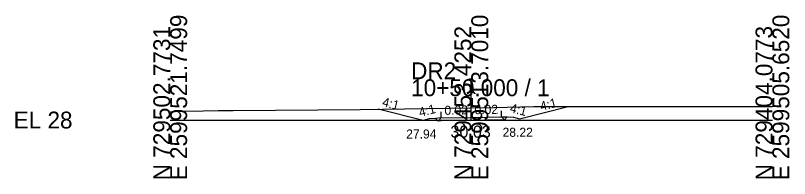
# Model space of a CAD drawing. Extents: x -26 to 1162, y -10 to 9515.
# Drawn here: x -25.7 to 102.8, y 2490.3 to 2517.3 of the extents above; entities that cross this region are included whole.
import ezdxf

# ---------------------------------------------------------------- set-up
doc = ezdxf.new("R2010")
doc.units = 0
for name, color, linetype in [('Exist Cross Section Cell', 7, 'Continuous'), ('Exist XS Center Line Elevation Label', 7, 'Continuous'), ('Exist XS Ground Line', 7, 'Continuous'), ('Prop XS Ditch Slope Text', 7, 'Continuous'), ('Prop XS Ditch Standard Text', 7, 'Continuous'), ('Prop XS Dump Level', 7, 'Continuous'), ('Prop XS EOT Tick Mark', 7, 'Continuous'), ('Prop XS Finish Grade', 7, 'Continuous'), ('Prop XS Finish Grade Earthwork', 7, 'Continuous'), ('Prop XS Finish Grade Pavement', 7, 'Continuous'), ('Prop XS Pvmt Edge Slope', 7, 'Continuous'), ('Prop XS SE Text', 7, 'Continuous'), ('Prop XS Side Slope Text', 7, 'Continuous'), ('Prop XS Subgrade Earthwork', 7, 'Continuous')]:
    doc.layers.add(name, color=color, linetype=linetype)

msp = doc.modelspace()

# ---------------------------------------------------------------- linework, layer by layer
at = {"layer": 'Exist Cross Section Cell'}
for p, q in [((50, 2500), (50, 2506.76)), ((0, 2500), (50, 2500)), ((50, 2500), (100, 2500))]:
    msp.add_line(p, q, dxfattribs=at)
at = {"layer": 'Exist XS Ground Line'}
msp.add_lwpolyline([(0, 2501.38), (1.63, 2501.48), (5.5, 2501.53), (7.99, 2501.56), (10.48, 2501.6), (31.55, 2501.76), (50, 2502.03), (53.78, 2502.09), (58.19, 2502.18), (60.37, 2502.22), (68.59, 2502.25), (86.19, 2502.24), (90.67, 2502.25), (100, 2502.25)], dxfattribs=at)
at = {"layer": 'Prop XS Dump Level'}
for p, q in [((45, 2500.35), (50, 2500.45)), ((50, 2500.45), (55, 2500.55))]:
    msp.add_line(p, q, dxfattribs=at)
at = {"layer": 'Prop XS EOT Tick Mark'}
for p, q in [((45, 2500.35), (45, 2501.35)), ((55, 2500.55), (55, 2501.55))]:
    msp.add_line(p, q, dxfattribs=at)
at = {"layer": 'Prop XS Finish Grade'}
for p, q in [((45, 2500.35), (44.05, 2500.27)), ((55, 2500.55), (55.95, 2500.51))]:
    msp.add_line(p, q, dxfattribs=at)
at = {"layer": 'Prop XS Finish Grade Earthwork'}
for p, q in [((42, 2499.94), (34.53, 2501.81)), ((58, 2500.22), (66.09, 2502.24)), ((43, 2500.19), (42, 2499.94)), ((44.05, 2500.27), (43, 2500.19)), ((55.95, 2500.51), (57, 2500.47)), ((57, 2500.47), (58, 2500.22))]:
    msp.add_line(p, q, dxfattribs=at)
at = {"layer": 'Prop XS Finish Grade Pavement'}
for p, q in [((45, 2500.35), (50, 2500.45)), ((50, 2500.45), (55, 2500.55))]:
    msp.add_line(p, q, dxfattribs=at)
at = {"layer": 'Prop XS Pvmt Edge Slope'}
for p, q in [((44.49, 2499.84), (44.05, 2500.27)), ((45, 2500.35), (44.49, 2499.84)), ((55, 2500.55), (55.49, 2500.06)), ((55.49, 2500.06), (55.95, 2500.51))]:
    msp.add_line(p, q, dxfattribs=at)
at = {"layer": 'Prop XS Subgrade Earthwork'}
for p, q in [((44.49, 2499.84), (44.05, 2500.27)), ((55, 2500.05), (50, 2499.95)), ((55, 2500.05), (55.49, 2500.06)), ((55.49, 2500.06), (55.95, 2500.51)), ((45, 2499.85), (44.49, 2499.84)), ((50, 2499.95), (45, 2499.85))]:
    msp.add_line(p, q, dxfattribs=at)

# ---------------------------------------------------------------- texts
at = {"layer": 'Exist Cross Section Cell'}
for s, p in [('E 2599521.7499', (2.8, 2490)), ('E 2599513.7010', (52.8, 2490)), ('E 2599505.6520', (102.8, 2490)), ('N 729502.7731', (0, 2490)), ('N 729453.4252', (50, 2490)), ('N 729404.0773', (100, 2490))]:
    msp.add_text(s, height=2.8, rotation=90, dxfattribs=at).set_placement(p)
for s, p in [('DR2', (40, 2506.76)), ('10+50.000 / 1', (40, 2503.96)), ('EL 28', (-26, 2498.6))]:
    msp.add_text(s, height=2.8, dxfattribs=at).set_placement(p)
at = {"layer": 'Exist XS Center Line Elevation Label'}
msp.add_text('30.03', height=2, dxfattribs=at).set_placement((46.54, 2497.08))
at = {"layer": 'Prop XS Ditch Slope Text'}
for rotation, p in [(14.0362, (41.49, 2500.52)), (345.9638, (56.3, 2501.33))]:
    msp.add_text('4:1', height=1.5, rotation=rotation, dxfattribs=at).set_placement(p)
at = {"layer": 'Prop XS Ditch Standard Text'}
for s, p in [('28.22', (55.19, 2497.22)), ('27.94', (39.19, 2496.94))]:
    msp.add_text(s, height=1.5, dxfattribs=at).set_placement(p)
at = {"layer": 'Prop XS Dump Level'}
for p in [(43, 2500.15), (57, 2500.43)]:
    msp.add_text('Case1', height=0.04, dxfattribs=at).set_placement(p)
at = {"layer": 'Prop XS SE Text'}
for p in [(50.55, 2500.96), (45.55, 2500.86)]:
    msp.add_text('0.02', height=1.5, rotation=1.1458, dxfattribs=at).set_placement(p)
at = {"layer": 'Prop XS Side Slope Text'}
for rotation, p in [(345.9638, (35.11, 2502.33)), (14.0362, (61.62, 2501.53))]:
    msp.add_text('4:1', height=1.5, rotation=rotation, dxfattribs=at).set_placement(p)

doc.saveas('drawing.dxf')
